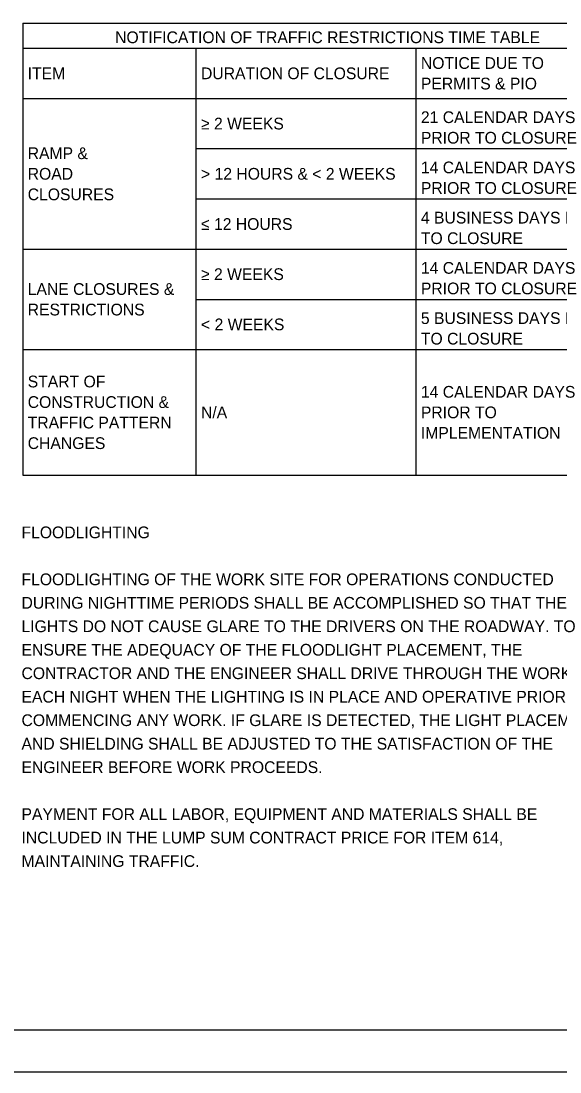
# Model space of a CAD drawing. Extents: x -26.4 to 34, y 0 to 22.
# Drawn here: x 17.25 to 23.67, y 0 to 12.53 of the extents above; entities that cross this region are included whole.
import ezdxf

# ---------------------------------------------------------------- set-up
doc = ezdxf.new("R2010")
doc.units = 0
for name, color, linetype in [('SH_Border', 7, 'Continuous'), ('SH_Cut_Line', 7, 'Continuous'), ('SH_Text', 7, 'Continuous')]:
    doc.layers.add(name, color=color, linetype=linetype)

msp = doc.modelspace()

# ---------------------------------------------------------------- linework, layer by layer
at = {"layer": 'SH_Border'}
msp.add_lwpolyline([(1.5, 21.5), (33.5, 21.5), (33.5, 0.5), (1.5, 0.5)], close=True, dxfattribs=at)
at = {"layer": 'SH_Cut_Line'}
msp.add_lwpolyline([(0, 0), (34, 0), (34, 22), (0, 22)], close=True, dxfattribs=at)
at = {"layer": 'SH_Text'}
for p, q in [((17.266, 12.508), (24.244, 12.508)), ((17.266, 12.508), (17.266, 7.118)), ((17.266, 12.209), (24.244, 12.209)), ((19.332, 12.209), (19.332, 7.118)), ((21.953, 12.209), (21.953, 7.118)), ((17.266, 11.61), (24.244, 11.61)), ((19.332, 11.011), (24.244, 11.011)), ((19.332, 10.412), (24.244, 10.412)), ((17.266, 9.813), (24.244, 9.813)), ((19.332, 9.214), (24.244, 9.214)), ((17.266, 8.615), (24.244, 8.615)), ((17.266, 7.118), (24.244, 7.118))]:
    msp.add_line(p, q, dxfattribs=at)

# ---------------------------------------------------------------- texts
for s, p in [('NOTIFICATION OF TRAFFIC RESTRICTIONS TIME TABLE', (18.368, 12.269)), ('NOTICE DUE TO ', (22.013, 11.962)), ('ITEM', (17.326, 11.839)), ('DURATION OF CLOSURE', (19.392, 11.839)), ('PERMITS & PIO', (22.013, 11.717)), ('21 CALENDAR DAYS ', (22.013, 11.316)), ('≥ 2 WEEKS', (19.392, 11.24)), ('PRIOR TO CLOSURE', (22.013, 11.071)), ('RAMP &', (17.326, 10.886)), ('ROAD', (17.326, 10.641)), ('> 12 HOURS & < 2 WEEKS', (19.392, 10.641)), ('14 CALENDAR DAYS ', (22.013, 10.717)), ('CLOSURES', (17.326, 10.396)), ('PRIOR TO CLOSURE', (22.013, 10.472)), ('≤ 12 HOURS', (19.392, 10.042)), ('4 BUSINESS DAYS PRIOR ', (22.013, 10.118)), ('TO CLOSURE', (22.013, 9.873)), ('14 CALENDAR DAYS ', (22.013, 9.519)), ('≥ 2 WEEKS', (19.392, 9.444)), ('LANE CLOSURES & ', (17.326, 9.267)), ('PRIOR TO CLOSURE', (22.013, 9.274)), ('RESTRICTIONS', (17.326, 9.022)), ('5 BUSINESS DAYS PRIOR ', (22.013, 8.92)), ('< 2 WEEKS', (19.392, 8.845)), ('TO CLOSURE', (22.013, 8.675)), ('START OF ', (17.326, 8.164)), ('14 CALENDAR DAYS ', (22.013, 8.041)), ('CONSTRUCTION & ', (17.326, 7.919)), ('N/A', (19.392, 7.796)), ('PRIOR TO ', (22.013, 7.796)), ('TRAFFIC PATTERN ', (17.326, 7.674)), ('IMPLEMENTATION', (22.013, 7.551)), ('CHANGES', (17.326, 7.429)), ('FLOODLIGHTING', (17.252, 6.365)), ('FLOODLIGHTING OF THE WORK SITE FOR OPERATIONS CONDUCTED ', (17.252, 5.805)), ('DURING NIGHTTIME PERIODS SHALL BE ACCOMPLISHED SO THAT THE ', (17.252, 5.525)), ('LIGHTS DO NOT CAUSE GLARE TO THE DRIVERS ON THE ROADWAY. TO ', (17.252, 5.245)), ('ENSURE THE ADEQUACY OF THE FLOODLIGHT PLACEMENT, THE ', (17.252, 4.965)), ('CONTRACTOR AND THE ENGINEER SHALL DRIVE THROUGH THE WORK SITE ', (17.252, 4.685)), ('EACH NIGHT WHEN THE LIGHTING IS IN PLACE AND OPERATIVE PRIOR TO ', (17.252, 4.405)), ('COMMENCING ANY WORK. IF GLARE IS DETECTED, THE LIGHT PLACEMENT ', (17.252, 4.125)), ('AND SHIELDING SHALL BE ADJUSTED TO THE SATISFACTION OF THE ', (17.252, 3.845)), ('ENGINEER BEFORE WORK PROCEEDS.', (17.252, 3.565)), ('PAYMENT FOR ALL LABOR, EQUIPMENT AND MATERIALS SHALL BE ', (17.252, 3.005)), ('INCLUDED IN THE LUMP SUM CONTRACT PRICE FOR ITEM 614, ', (17.252, 2.725)), ('MAINTAINING TRAFFIC.', (17.252, 2.445))]:
    msp.add_text(s, height=0.14, dxfattribs=at).set_placement(p)

doc.saveas('drawing.dxf')
